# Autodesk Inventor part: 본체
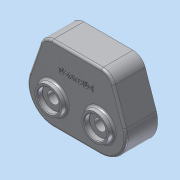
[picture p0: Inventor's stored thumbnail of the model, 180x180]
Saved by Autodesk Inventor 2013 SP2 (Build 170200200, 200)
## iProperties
Created: 2014-12
Part Number: 본체
Material: 알루미늄 6061
Document SubType Name: Modeling
Designer: dgall
Density: 2.71 g/cm^3
Mass: 613.443 g
Surface Area: 665.018 cm^2
Volume: 226.363 cm^3
Author: dgall
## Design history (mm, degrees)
sketch "스케치1"
  geometry: L1 (47, 36)-(-47, 36); L2 (-47, 36)-(-66.565, -20.803); L3 (-32.527, -68.527)-(32.527, -68.527); L4 (66.565, -20.803)-(47, 36); L5 (32.527, -32.527)-(0, 0); L6 (0, 0)-(-32.527, -32.527); A1 r 36 centre (-32.527, -32.527) between (-66.565, -20.803) and (-32.527, -68.527); A2 r 36 centre (32.527, -32.527) between (32.527, -68.527) and (66.565, -20.803); 2 further points
  constraints: 12 end point, 4 point on circle, 4 tangent, 2 centre point, 2 midpoint, 2 vertical alignment, 1 equal length, 1 equal radius, 1 horizontal, 1 parallel
  dimensions: "d0" = 90 deg angle of L6 L5; "d1" = 36 radius of A1; "d3" = 94 distance of L1.start L1.end; "d4" = 36 distance from line of L5.end L1; "d5" = 46 distance of L5.start L5.end
extrude "돌출1" new body sketch "스케치1" distance "d6" = 44; taper "d7" = 0 deg
sketch "스케치2"
  geometry: L1 (-47, -36)-(47, -36) reference; L2 (47, -36)-(66.565, 20.803) reference; L3 (32.527, 68.527)-(-32.527, 68.527) reference; L4 (-66.565, 20.803)-(-47, -36) reference; L5 (-32.527, 63.527)-(32.527, 63.527); L6 (61.837, 22.432)-(43.434, -31); L7 (43.434, -31)-(-43.434, -31); L8 (-43.434, -31)-(-61.837, 22.432); A1 r 36 centre (32.527, 32.527) between (66.565, 20.803) and (32.527, 68.527) reference; A2 r 36 centre (-32.527, 32.527) between (-32.527, 68.527) and (-66.565, 20.803) reference; A3 r 31 centre (32.527, 32.527) between (61.837, 22.432) and (32.527, 63.527); A4 r 31 centre (-32.527, 32.527) between (-32.527, 63.527) and (-61.837, 22.432); 1 further point
  constraints: 8 end point, 4 point on circle, 2 centre point, 5 other
  dimensions: "d8" = 5 distance between parallel lines of L1 L7
extrude "돌출2" cut sketch "스케치2" distance "d9" = 34; taper "d10" = 0 deg
sketch "스케치3"
  geometry: A1 r 31 centre (-32.527, 32.527) between (-32.527, 63.527) and (-61.837, 22.432) reference; A2 r 31 centre (32.527, 32.527) between (61.837, 22.432) and (32.527, 63.527) reference; A3 r 24 centre (32.527, 32.527) between (21.111, 11.416) and (11.416, 21.111); A4 r 24 centre (-32.527, 32.527) between (-11.416, 21.111) and (-21.111, 11.416); A5 r 24 centre (0, 0) between (11.416, 21.111) and (-11.416, 21.111); A6 r 24 centre (0, 0) between (-21.111, 11.416) and (21.111, 11.416); 1 further point
  constraints: 8 point on circle, 4 centre point, 3 coincident, 3 equal radius
  dimensions: "d13" = 24 radius of A6
extrude "돌출3" join sketch "스케치3" distance "d17" = 11; taper "d18" = 0 deg
hole "구멍1" diameter "d21" = 20; stored, may be unused: countersink angle "d25" = 90 deg, drill point angle "d27" = 0 deg; dims "d19" = 10, "d20" = 10, "d22" = 6, "d23" = 40, "d24" = 12, "d26" = 15
hole "구멍2" diameter "d30" = 15.5; stored, may be unused: countersink angle "d34" = 90 deg, drill point angle "d36" = 0 deg; dims "d28" = 10, "d29" = 10, "d31" = 6, "d32" = 35, "d33" = 11, "d35" = 21
hole "구멍3" diameter "d39" = 15.5; stored, may be unused: countersink angle "d43" = 90 deg, drill point angle "d45" = 0 deg; dims "d37" = 10, "d38" = 10, "d40" = 6, "d41" = 35, "d42" = 11, "d44" = 21
sketch "스케치4"
  geometry: L1 (-32.527, 63.527)-(32.527, 63.527) reference; L2 (61.837, 22.432)-(43.434, -31) reference; L3 (-43.434, -31)-(-61.837, 22.432) reference; L4 (-47, -36)-(47, -36) reference; A1 r 8 centre (-51.7, -7) between (-49.095, -14.564) and (-54.305, 0.564); A2 r 8 centre (51.7, -7) between (54.305, 0.564) and (49.095, -14.564); A3 r 8 centre (0, 63.527) between (-8, 63.527) and (8, 63.527); 1 further point
  constraints: 8 point on line, 6 point on circle, 3 centre point, 2 equal radius, 1 midpoint
  dimensions: "d69" = 29 distance from line of A1.centre L4; "d70" = 8 radius of A1; "d71" = 29 distance from line of A2.centre L4
extrude "돌출4" join sketch "스케치4" distance "d72" = 34; taper "d73" = 0 deg
hole "구멍6" diameter "d76" = 4.134; stored, may be unused: countersink angle "d80" = 90 deg, drill point angle "d82" = 118 deg; dims "d74" = 10, "d75" = 10, "d77" = 20, "d78" = 35, "d79" = 11, "d81" = 23
hole "구멍7" diameter "d85" = 4.134; stored, may be unused: countersink angle "d89" = 90 deg, drill point angle "d91" = 118 deg; dims "d83" = 10, "d84" = 10, "d86" = 20, "d87" = 35, "d88" = 11, "d90" = 23
hole "구멍8" diameter "d94" = 4.134; stored, may be unused: countersink angle "d98" = 90 deg, drill point angle "d100" = 118 deg; dims "d92" = 10, "d93" = 10, "d95" = 20, "d96" = 35, "d97" = 11, "d99" = 23
sketch "스케치5"
  geometry: C1 r 7.75 at (32.527, -32.527) reference; C2 r 7.75 at (-32.527, -32.527) reference; C3 r 20 at (-32.527, -32.527); C4 r 20 at (32.527, -32.527); A1 r 36 centre (-32.527, -32.527) between (-66.565, -20.803) and (-32.527, -68.527) reference; A2 r 36 centre (32.527, -32.527) between (32.527, -68.527) and (66.565, -20.803) reference; 1 further point
  constraints: 2 centre point, 2 coincident
  dimensions: "d101" = 40 diameter of C3; "d104" = 40 diameter of C4
extrude "돌출5" join sketch "스케치5" distance "d105" = 7; taper "d106" = -10 deg
hole "구멍9" diameter "d109" = 30; stored, may be unused: countersink angle "d113" = 90 deg, drill point angle "d115" = 0 deg; dims "d107" = 10, "d108" = 10, "d110" = 20, "d111" = 35, "d112" = 11, "d114" = 7
hole "구멍10" diameter "d118" = 30; stored, may be unused: countersink angle "d122" = 90 deg, drill point angle "d124" = 0 deg; dims "d116" = 10, "d117" = 10, "d119" = 20, "d120" = 35, "d121" = 11, "d123" = 7
chamfer "모따기1" distance "d64" = 1; stored, may be unused: second distance "d65" = 2, angle "d66" = 45 deg
fillet "모깎기1" dims "d125" = 18, "d126" = 13
fillet "모깎기2" dims "d127" = 3
fillet "모깎기3" dims "d128" = 3
fillet "모깎기4" dims "d129" = 3
fillet "모깎기5" dims "d130" = 0.3
node "작업 평면1"
sketch "스케치6"
  geometry: L1 (34.162, 36)-(-34.162, 36) reference; 2 further points
  constraints: 1 vertical alignment, 1 other
  dimensions: "d132" = 30 distance from line of point (0, 6) L1
feature "엠보싱1" sketch "스케치6" dims "d0" = 90 deg, "d1" = 36, "d3" = 94, "d4" = 36, "d5" = 46, "d8" = 5, "d133" = 1, "d134" = 0
node "솔리드1"
other parameters: "d11" = 48, "d131" = 15.75
